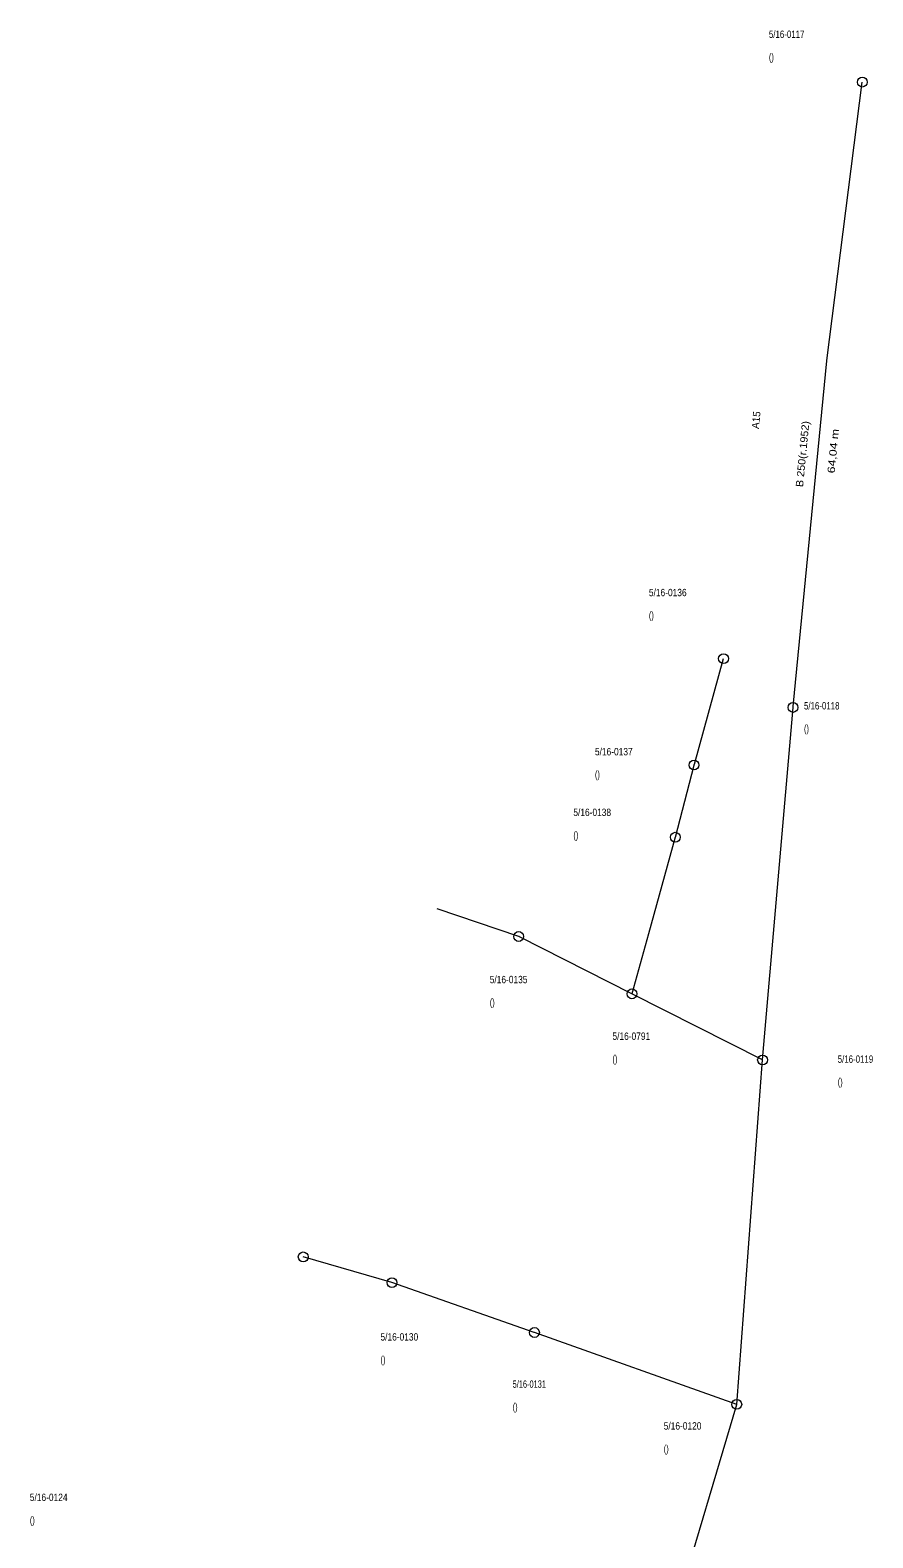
# Model space of a CAD drawing. Extents: x -710854 to -709799, y -1117012 to -1115891.
# Drawn here: x -710360.7 to -710274.9, y -1116298.3 to -1116144.9 of the extents above; entities that cross this region are included whole.
import ezdxf
from ezdxf.enums import TextEntityAlignment as Align

# ---------------------------------------------------------------- set-up
doc = ezdxf.new("R2010")
doc.units = 0
doc.header["$LTSCALE"] = 0.3
doc.layers.add('38', color=7, linetype='Continuous', lineweight=13)
doc.layers.add('44', color=7, linetype='Continuous', lineweight=13)
doc.layers.add('48', color=7, linetype='Continuous')

msp = doc.modelspace()

# ---------------------------------------------------------------- linework, layer by layer
at = {"layer": '38'}
for p, q in [((-710286.16, -1116249.67), (-710283.058, -1116213.795)), ((-710310.974, -1116237.105), (-710319.269, -1116234.284)), ((-710286.16, -1116249.67), (-710299.45, -1116242.94)), ((-710288.78, -1116284.72), (-710286.16, -1116249.67)), ((-710288.78, -1116284.72), (-710309.371, -1116277.403))]:
    msp.add_line(p, q, dxfattribs=at)
for points in [[(-710283.058, -1116213.795), (-710283.05, -1116213.7), (-710279.624, -1116178.509), (-710279.62, -1116178.47), (-710276.01, -1116150.15)], [(-710293.127, -1116219.653), (-710293.11, -1116219.59), (-710293.1, -1116219.55), (-710290.13, -1116208.82)], [(-710295.037, -1116227), (-710295.033, -1116226.983), (-710293.127, -1116219.653)], [(-710295.037, -1116227), (-710295.04, -1116227.01), (-710297.756, -1116236.821), (-710299.45, -1116242.94)], [(-710299.45, -1116242.94), (-710310.884, -1116237.143), (-710310.93, -1116237.12), (-710310.974, -1116237.105)], [(-710323.866, -1116272.325), (-710323.88, -1116272.32), (-710323.883, -1116272.319), (-710332.9, -1116269.71)], [(-710309.371, -1116277.403), (-710309.38, -1116277.4), (-710309.392, -1116277.396), (-710323.866, -1116272.325)], [(-710294.973, -1116305.64), (-710294.97, -1116305.63), (-710288.78, -1116284.72)]]:
    msp.add_lwpolyline(points, dxfattribs=at)
at = {"layer": '44'}
for centre in [(-710276.01, -1116150.15), (-710290.13, -1116208.82), (-710283.058, -1116213.795), (-710293.127, -1116219.653), (-710295.037, -1116227), (-710310.974, -1116237.105), (-710299.45, -1116242.94), (-710286.16, -1116249.67), (-710332.9, -1116269.71), (-710323.866, -1116272.325), (-710309.371, -1116277.403), (-710288.78, -1116284.72)]:
    msp.add_circle(centre, 0.5, dxfattribs=at)

# ---------------------------------------------------------------- texts
at = {"layer": '48'}
for s, width, p in [('5/16-0117', 0.8, (-710285.511, -1116145.654)), ('()', 0.7, (-710285.511, -1116147.965)), ('5/16-0136', 0.85, (-710297.725, -1116202.472)), ('()', 0.7, (-710297.725, -1116204.782)), ('5/16-0118', 0.8, (-710281.943, -1116214)), ('()', 0.7, (-710281.943, -1116216.31)), ('5/16-0137', 0.85, (-710303.215, -1116218.666)), ('()', 0.7, (-710303.215, -1116220.976)), ('5/16-0138', 0.85, (-710305.411, -1116224.842)), ('()', 0.7, (-710305.411, -1116227.152)), ('5/16-0135', 0.85, (-710313.92, -1116241.859)), ('()', 0.7, (-710313.92, -1116244.169)), ('5/16-0791', 0.85, (-710301.431, -1116247.624)), ('()', 0.7, (-710301.431, -1116249.934)), ('5/16-0119', 0.8, (-710278.512, -1116249.957)), ('()', 0.7, (-710278.512, -1116252.267)), ('5/16-0130', 0.85, (-710325.036, -1116278.228)), ('()', 0.7, (-710325.036, -1116280.538)), ('5/16-0131', 0.75, (-710311.587, -1116283.031)), ('()', 0.7, (-710311.587, -1116285.341)), ('5/16-0120', 0.85, (-710296.216, -1116287.286)), ('()', 0.7, (-710296.216, -1116289.596)), ('5/16-0124', 0.85, (-710360.718, -1116294.559)), ('()', 0.7, (-710360.718, -1116296.869))]:
    msp.add_text(s, height=0.75, dxfattribs=dict(at, width=width)).set_placement(p)
msp.add_text('A15', height=0.75, rotation=84.44, dxfattribs=at).set_placement((-710286.4445, -1116184.5798), align=Align.CENTER)
for s, width, p in [('B 250(r.1952)', 1.1, (-710281.7172, -1116188.0358)), ('64,04 m', 1.25, (-710278.6028, -1116187.7363))]:
    msp.add_text(s, height=0.75, rotation=84.44, dxfattribs=dict(at, width=width)).set_placement(p, align=Align.CENTER)

doc.saveas('drawing.dxf')
